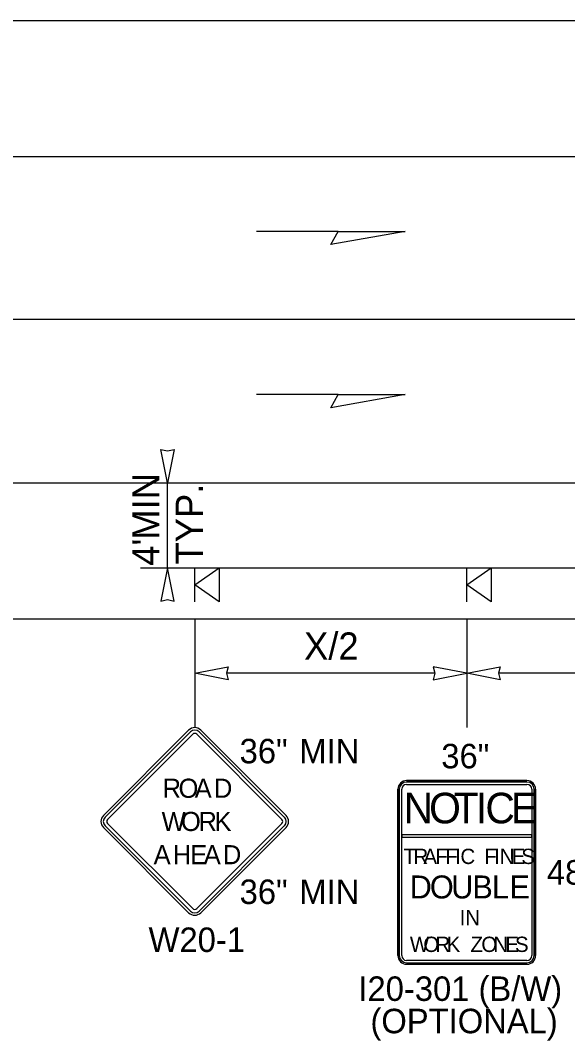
# Model space of a CAD drawing. Extents: x 99999.1 to 100055.7, y 99995 to 100010.7.
# Drawn here: x 100002.662 to 100004.272, y 100003.995 to 100006.996 of the extents above; entities that cross this region are included whole.
import ezdxf

# ---------------------------------------------------------------- set-up
doc = ezdxf.new("R2010")
doc.units = 0
for name, color, linetype in [('RD_ED_ShoulderPavedEdge', 7, 'Continuous'), ('RD_MK_LineEdgeWhite', 7, 'Continuous'), ('RD_MK_LineEdgeYellow', 7, 'Continuous'), ('RD_MK_LineLane', 7, 'Continuous'), ('TR_SN_ConstructionSigns', 7, 'Continuous'), ('TR_WZ_PortableSignMountBlk-Org', 7, 'Continuous'), ('TR_WZ_PortableSignMountBlk-Wht', 7, 'Continuous'), ('TR_WZ_WorkZoneDetails', 7, 'Continuous'), ('TR_WZ_WorkZoneTextCurrent', 7, 'Continuous')]:
    doc.layers.add(name, color=color, linetype=linetype)

msp = doc.modelspace()

# ---------------------------------------------------------------- linework, layer by layer
at = {"layer": 'RD_ED_ShoulderPavedEdge'}
for p, q in [((100000.8283, 100006.9957), (100015.62, 100006.9957)), ((100000.8283, 100005.2357), (100015.62, 100005.2357))]:
    msp.add_line(p, q, dxfattribs=at)
at = {"layer": 'RD_MK_LineEdgeWhite'}
msp.add_line((100000.8283, 100005.6357), (100015.62, 100005.6357), dxfattribs=at)
at = {"layer": 'RD_MK_LineEdgeYellow'}
msp.add_line((100000.8283, 100006.5957), (100015.62, 100006.5957), dxfattribs=at)
at = {"layer": 'RD_MK_LineLane'}
msp.add_lwpolyline([(100015.62, 100006.1157), (100000.8283, 100006.1157)], dxfattribs=at)
at = {"layer": 'TR_SN_ConstructionSigns'}
for p, q in [((100003.1574, 100004.9083), (100002.9068, 100004.6577)), ((100003.1624, 100004.9033), (100002.9118, 100004.6528)), ((100002.9187, 100004.6458), (100003.1693, 100004.8964)), ((100003.1812, 100004.8964), (100003.4318, 100004.6458)), ((100003.4388, 100004.6528), (100003.1882, 100004.9033)), ((100003.4438, 100004.6577), (100003.1932, 100004.9083)), ((100003.7981, 100004.76), (100004.1525, 100004.76)), ((100004.1525, 100004.76), (100003.7981, 100004.76)), ((100004.1525, 100004.76), (100003.7981, 100004.76)), ((100003.7728, 100004.2453), (100003.7728, 100004.7347)), ((100003.7728, 100004.7347), (100003.7728, 100004.2453)), ((100003.7728, 100004.7347), (100003.7728, 100004.2453)), ((100003.777, 100004.7347), (100003.777, 100004.2453)), ((100003.784, 100004.6004), (100003.784, 100004.7347)), ((100004.1525, 100004.7558), (100003.7981, 100004.7558)), ((100003.7981, 100004.7488), (100004.1525, 100004.7488)), ((100004.1665, 100004.7347), (100004.1665, 100004.6004)), ((100004.1736, 100004.2453), (100004.1736, 100004.7347)), ((100004.1778, 100004.7347), (100004.1778, 100004.2453)), ((100004.1778, 100004.2453), (100004.1778, 100004.7347)), ((100004.1778, 100004.2453), (100004.1778, 100004.7347)), ((100002.9068, 100004.6219), (100003.1574, 100004.3714)), ((100002.9118, 100004.6269), (100003.1624, 100004.3763)), ((100003.1693, 100004.3833), (100002.9187, 100004.6339)), ((100003.4318, 100004.6339), (100003.1812, 100004.3833)), ((100003.1882, 100004.3763), (100003.4388, 100004.6269)), ((100003.1932, 100004.3714), (100003.4438, 100004.6219)), ((100003.784, 100004.6004), (100003.784, 100004.6004)), ((100004.1665, 100004.6004), (100003.784, 100004.6004)), ((100003.784, 100004.6004), (100003.784, 100004.5934)), ((100003.784, 100004.5934), (100003.784, 100004.6004)), ((100003.784, 100004.5934), (100004.1665, 100004.5934)), ((100003.784, 100004.2453), (100003.784, 100004.5934)), ((100004.1665, 100004.5934), (100004.1665, 100004.6004)), ((100004.1665, 100004.6004), (100004.1665, 100004.5934)), ((100004.1665, 100004.5934), (100004.1665, 100004.2453)), ((100004.1525, 100004.2313), (100003.7981, 100004.2313)), ((100003.7981, 100004.2242), (100004.1525, 100004.2242)), ((100004.1525, 100004.22), (100003.7981, 100004.22)), ((100003.7981, 100004.22), (100004.1525, 100004.22)), ((100003.7981, 100004.22), (100004.1525, 100004.22))]:
    msp.add_line(p, q, dxfattribs=at)
for centre, radius, start, end in [((100003.1753, 100004.8904), 0.0253, 45, 135), ((100003.1753, 100004.8904), 0.0183, 45, 135), ((100003.1753, 100004.8904), 0.00844, 45, 135), ((100003.7981, 100004.7347), 0.0253, 90, 180), ((100003.7981, 100004.7347), 0.0253, 90, 180), ((100003.7981, 100004.7347), 0.0253, 90, 180), ((100004.1525, 100004.7347), 0.0253, 0, 90), ((100004.1525, 100004.7347), 0.0253, 0, 90), ((100004.1525, 100004.7347), 0.0253, 0, 90), ((100003.7981, 100004.7347), 0.0211, 90, 180), ((100003.7981, 100004.7347), 0.0141, 90, 180), ((100004.1525, 100004.7347), 0.0211, 0, 90), ((100004.1525, 100004.7347), 0.0141, 0, 90), ((100002.9247, 100004.6398), 0.0253, 135, 225), ((100002.9247, 100004.6398), 0.0183, 135, 225), ((100002.9247, 100004.6398), 0.00844, 135, 225), ((100003.4259, 100004.6398), 0.00844, 315, 45), ((100003.4259, 100004.6398), 0.0183, 315, 45), ((100003.4259, 100004.6398), 0.0253, 315, 45), ((100003.1753, 100004.3893), 0.0253, 225, 315), ((100003.1753, 100004.3893), 0.0183, 225, 315), ((100003.1753, 100004.3893), 0.00844, 225, 315), ((100003.7981, 100004.2453), 0.0253, 180, 270), ((100003.7981, 100004.2453), 0.0253, 180, 270), ((100003.7981, 100004.2453), 0.0253, 180, 270), ((100003.7981, 100004.2453), 0.0211, 180, 270), ((100003.7981, 100004.2453), 0.0141, 180, 270), ((100004.1525, 100004.2453), 0.0253, 270, 0), ((100004.1525, 100004.2453), 0.0253, 270, 0), ((100004.1525, 100004.2453), 0.0211, 270, 0), ((100004.1525, 100004.2453), 0.0141, 270, 0), ((100004.1525, 100004.2453), 0.0253, 270, 0)]:
    msp.add_arc(centre, radius, start, end, dxfattribs=at)
at = {"layer": 'TR_WZ_PortableSignMountBlk-Org'}
msp.add_line((100003.1753, 100005.2858), (100003.1753, 100005.3858), dxfattribs=at)
msp.add_lwpolyline([(100003.1753, 100005.3357), (100003.2471, 100005.3858), (100003.2471, 100005.2858)], close=True, dxfattribs=at)
at = {"layer": 'TR_WZ_PortableSignMountBlk-Wht'}
msp.add_line((100003.9753, 100005.2857), (100003.9753, 100005.3857), dxfattribs=at)
msp.add_lwpolyline([(100003.9753, 100005.3356), (100004.0471, 100005.3857), (100004.0471, 100005.2857)], close=True, dxfattribs=at)
at = {"layer": 'TR_WZ_WorkZoneDetails'}
for p, q in [((100003.5976, 100006.375), (100003.3565, 100006.375)), ((100003.5976, 100005.895), (100003.3565, 100005.895)), ((100003.0153, 100005.6357), (100003.1753, 100005.6357)), ((100003.0953, 100005.3858), (100003.0953, 100005.6357)), ((100003.0153, 100005.3858), (100003.1753, 100005.3858)), ((100003.1753, 100005.3858), (100006.6368, 100005.3858)), ((100003.1753, 100005.2357), (100003.1753, 100004.9157)), ((100003.9753, 100005.236), (100003.9753, 100004.9157)), ((100003.8815, 100005.0757), (100003.269, 100005.0757)), ((100004.6815, 100005.0757), (100004.069, 100005.0757))]:
    msp.add_line(p, q, dxfattribs=at)
for points in [[(100003.7941, 100006.375), (100003.5753, 100006.3364), (100003.5976, 100006.375)], [(100003.7941, 100005.895), (100003.5753, 100005.8564), (100003.5976, 100005.895)], [(100003.0953, 100005.6357), (100003.076, 100005.734), (100003.0953, 100005.7295), (100003.1146, 100005.734)], [(100003.0953, 100005.3858), (100003.076, 100005.2875), (100003.0953, 100005.2921), (100003.1146, 100005.2875)], [(100003.1753, 100005.0757), (100003.2736, 100005.095), (100003.269, 100005.0757), (100003.2736, 100005.0565)], [(100003.9753, 100005.0757), (100003.877, 100005.095), (100003.8815, 100005.0757), (100003.877, 100005.0565)], [(100003.9753, 100005.0757), (100004.0736, 100005.095), (100004.069, 100005.0757), (100004.0736, 100005.0565)]]:
    msp.add_lwpolyline(points, close=True, dxfattribs=at)

# ---------------------------------------------------------------- texts
at = {"layer": 'TR_SN_ConstructionSigns'}
for s, p in [('36"', (100003.3073, 100004.8107)), ('MIN', (100003.4829, 100004.8107)), ('36"', (100003.9005, 100004.796)), ('48"', (100004.211, 100004.454)), ('36"', (100003.3073, 100004.397)), ('MIN', (100003.4829, 100004.397)), ('W20-1', (100003.0395, 100004.2559)), ('I20-301 (B/W)', (100003.6567, 100004.112)), ('(OPTIONAL)', (100003.6921, 100004.0169))]:
    msp.add_text(s, height=0.072, rotation=360, dxfattribs=at).set_placement(p)
for s, height, p in [('R', 0.0562, (100003.0807, 100004.7094)), ('O', 0.0562, (100003.1276, 100004.7094)), ('A', 0.0562, (100003.1751, 100004.7094)), ('D', 0.0562, (100003.2316, 100004.7094)), ('N', 0.09, (100003.7895, 100004.6342)), ('O', 0.09, (100003.8646, 100004.6342)), ('T', 0.09, (100003.9367, 100004.6342)), ('I', 0.09, (100004.0019, 100004.6342)), ('C', 0.09, (100004.0302, 100004.6342)), ('E', 0.09, (100004.1052, 100004.6342)), ('O', 0.0562, (100003.1347, 100004.6117)), ('W', 0.0562, (100003.0778, 100004.6117)), ('R', 0.0562, (100003.1862, 100004.6117)), ('K', 0.0562, (100003.2334, 100004.6117)), ('A', 0.0562, (100003.0543, 100004.514)), ('H', 0.0562, (100003.1106, 100004.514)), ('E', 0.0562, (100003.1623, 100004.514)), ('A', 0.0562, (100003.2017, 100004.514)), ('D', 0.0562, (100003.258, 100004.514)), ('T', 0.045, (100003.7894, 100004.5146)), ('R', 0.045, (100003.8187, 100004.5146)), ('A', 0.045, (100003.8479, 100004.5146)), ('F', 0.045, (100003.883, 100004.5146)), ('F', 0.045, (100003.9123, 100004.5146)), ('I', 0.045, (100003.9415, 100004.5146)), ('C', 0.045, (100003.9568, 100004.5146)), ('F', 0.045, (100004.027, 100004.5146)), ('I', 0.045, (100004.0563, 100004.5146)), ('N', 0.045, (100004.0725, 100004.5146)), ('E', 0.045, (100004.1076, 100004.5146)), ('S', 0.045, (100004.1359, 100004.5146)), ('D', 0.0675, (100003.8075, 100004.4134)), ('O', 0.0675, (100003.8669, 100004.4134)), ('U', 0.0675, (100003.9297, 100004.4134)), ('B', 0.0675, (100003.9918, 100004.4134)), ('L', 0.0675, (100004.0492, 100004.4134)), ('E', 0.0675, (100004.1012, 100004.4134)), ('I', 0.045, (100003.9546, 100004.3346)), ('N', 0.045, (100003.9708, 100004.3346)), ('W', 0.045, (100003.8081, 100004.2559)), ('O', 0.045, (100003.8477, 100004.2559)), ('R', 0.045, (100003.8833, 100004.2559)), ('K', 0.045, (100003.9161, 100004.2559)), ('Z', 0.045, (100003.9863, 100004.2559)), ('O', 0.045, (100004.0183, 100004.2559)), ('N', 0.045, (100004.0538, 100004.2559)), ('E', 0.045, (100004.0889, 100004.2559)), ('S', 0.045, (100004.1173, 100004.2559))]:
    msp.add_text(s, height=height, dxfattribs=at).set_placement(p)
at = {"layer": 'TR_WZ_WorkZoneTextCurrent'}
for s, rotation, p in [('MIN', 90, (100003.0713, 100005.4682)), ('TYP.', 90, (100003.1993, 100005.3954)), ("4'", 90, (100003.0713, 100005.3917)), ('X/2', 360, (100003.4968, 100005.1157))]:
    msp.add_text(s, height=0.08, rotation=rotation, dxfattribs=at).set_placement(p)

doc.saveas('drawing.dxf')
